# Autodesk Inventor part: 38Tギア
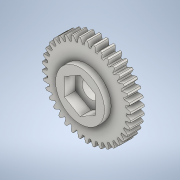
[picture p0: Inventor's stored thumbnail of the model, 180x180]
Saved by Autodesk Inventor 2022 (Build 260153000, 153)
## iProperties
CustomPartVersion: 1
Created: 2024-10
Part Number: 38Tギア
Material: Steel
Document SubType Name: Modeling
Designer: shimizu
Categories: <?xml version="1.0" encoding="UTF-16"?> <MemberInstance><Categories><FamilyTemplate><FamilyTemplateParameter ValueType="xs:double" Id="1" ObjectReferenceKey="da
Density: 1 g/cm^3
Appearance: Steel
Author: shimizu
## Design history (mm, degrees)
sketch "Sketch1"
  geometry: C1 r 10 at (0, 0)
  constraints: 1 centre point
  dimensions: "d0" = 20 diameter of C1 (= da_da)
extrude "Extrusion1" new body sketch "Sketch1" distance "d1" = 3 (= da_b); taper "d2" = 0 deg
workplane "Work Plane2"
sketch "Sketch2"
  geometry: C1 r 10 at (0, 0) reference; C2 r 9.5 at (0, 0)
  constraints: 1 centre point, 1 coincident
  dimensions: "d3" = 19 diameter of C2 (= da_d)
feature "ピッチ円直径" sketch "Sketch2" dims "d4" = 10, "d5" = 0
workplane "Work Plane8"
workplane "Work Plane9"
feature "平歯車" dims "da_b" = 3, "da_d" = 19, "da_aw" = 23.75, "da_da" = 20, "da_df" = 17.75, "da_dw" = 19, angle "da_beta" = 0 deg, "da_lefttooth" = 0, "da_righttooth" = 0
sketch "スケッチ3"
  geometry: C1 r 5.5 at (0, 0); 1 further point
  constraints: 1 centre point, 1 coincident
  dimensions: "d49" = 11 diameter of C1
extrude "押し出し2" join sketch "スケッチ3" distance "d50" = 1.5; taper "d51" = 0 deg
sketch "スケッチ4"
  geometry: C1 r 2 at (0, 0); 1 further point
  constraints: 1 centre point, 1 coincident
  dimensions: "d52" = 4 diameter of C1
extrude "押し出し3" cut sketch "スケッチ4" extent not by distance; stored distance "d53" = 0; taper "d54" = 0 deg
sketch "スケッチ5"
  geometry: L1 (0, -4.041)-(-3.5, -2.021); L2 (-3.5, -2.021)-(-3.5, 2.021); L3 (-3.5, 2.021)-(0, 4.041); L4 (0, 4.041)-(3.5, 2.021); L5 (3.5, 2.021)-(3.5, -2.021); L6 (3.5, -2.021)-(0, -4.041); 2 further points
  constraints: 12 end point, 1 coincident, 1 vertical alignment, 13 other
  dimensions: "d55" = 7 distance between parallel lines of L5 L2
extrude "押し出し4" cut sketch "スケッチ5" distance "d56" = 2.5; taper "d57" = 0 deg
body "Solid1"
body "Srf1"
other parameters: "d16" = 23.75 (= da_aw), "d17" = 0, "d34" = 0.82673 (computed from da_z), "d39" = 0, "d41" = 0, "d43" = 23.75 (= da_aw), "d46" = 23.75 (= da_aw), "d47" = 0, "d48" = 0
